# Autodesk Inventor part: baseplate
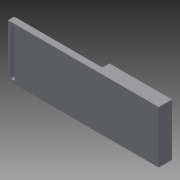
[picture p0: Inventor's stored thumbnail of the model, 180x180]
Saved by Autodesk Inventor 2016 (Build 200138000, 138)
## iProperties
Created: 2014-07
Part Number: baseplate
Material: Generic
Document SubType Name: Modeling
Designer: James
Density: 1 g/cm^3
Appearance: Default
Author: James
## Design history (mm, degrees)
sketch "Sketch1"
  geometry: L1 (-103.334, 41.944)-(116.666, 41.944); L2 (116.666, 41.944)-(116.666, -34.256); L3 (116.666, -34.256)-(-103.334, -34.256); L4 (-103.334, -34.256)-(-103.334, 41.944); 1 further point
  constraints: 8 end point, 2 parallel, 1 horizontal, 1 perpendicular
  dimensions: "d0" = 76.2 distance between parallel lines of L3 L1; "d1" = 220 distance between parallel lines of L2 L4
extrude "Extrusion1" new body sketch "Sketch1" distance "d2" = 10; taper "d3" = 0 deg
sketch "Sketch3"
  geometry: L1 (103.334, -41.944)-(103.334, 34.256) reference; L2 (103.334, 34.256)-(-116.666, 34.256) reference; L3 (103.334, 34.256)-(1.734, 34.256); L4 (1.734, 34.256)-(1.734, -41.944); L5 (1.734, -41.944)-(103.334, -41.944); L6 (103.334, -41.944)-(103.334, 34.256); 3 further points
  constraints: 8 end point, 2 parallel, 1 horizontal, 1 perpendicular
  dimensions: "d13" = 76.2 distance between parallel lines of L3 L5; "d14" = 101.6 distance between parallel lines of L1 L4; "d15" = 38.1 distance from line of L1 point (65.234, -3.844); "d16" = 38.1 distance from line of L2 point (65.234, -3.844); "d17" = 25.4 distance of point (65.234, -3.844) point (39.834, -3.844); "d18" = 38.1 distance from line of L2 point (39.834, -3.844)
extrude "Extrusion3" join sketch "Sketch3" distance "d26" = 11.5; taper "d27" = 0 deg
sketch "Sketch4"
  geometry: L1 (103.334, 34.256)-(1.734, 34.256) reference; L2 (103.334, -41.944)-(103.334, 34.256) reference; 3 further points
  dimensions: "d28" = 38.1 distance from line of L2 point (65.234, -3.844); "d29" = 38.1 distance from line of L1 point (65.234, -3.844); "d30" = 38.1 distance from line of L1 point (39.834, -3.844); "d31" = 25.4 distance of point (65.234, -3.844) point (39.834, -3.844)
hole "Hole2" sketch "Sketch4" at (65.234, -3.844), (39.834, -3.844) diameter "d32" = 4.917; stored, may be unused: countersink angle "d36" = 90 deg, drill point angle "d38" = 118 deg; dims "d33" = 6, "d34" = 4, "d35" = 2, "d37" = 15
sketch "Sketch7"
  geometry: L1 (1.734, -41.944)-(1.734, 34.256) reference; L2 (1.734, 34.256)-(-116.666, 34.256) reference; L3 (-116.666, -41.944)-(1.734, -41.944) reference; L4 (1.734, 6.111)-(-18.266, 6.111); L5 (-18.266, 6.111)-(-18.266, -10.434); L6 (-18.266, -10.434)-(1.734, -10.434); L7 (1.734, -10.434)-(1.734, 6.111); L8 (-18.266, -7.069)-(-64.266, -7.069); L9 (-64.266, -7.069)-(-64.266, -2.161); L10 (-64.266, -2.161)-(-18.266, -2.161); L11 (-18.266, -2.161)-(-18.266, -7.069); L12 (-64.266, 7.156)-(-64.266, -14.844); 3 further points
  constraints: 18 end point, 5 parallel, 2 coincident, 2 horizontal, 2 perpendicular, 2 point on line
  dimensions: "d46" = 20 distance between parallel lines of L7 L5; "d47" = 46 distance between parallel lines of L11 L9; "d48" = 27.1 distance from line of L3 L12.end; "d49" = 27.1 distance from line of L2 L12.start (= d48); "d57" = 0 distance between parallel lines of L12 L9
hole "Hole3" sketch "Sketch7" at (-64.266, 7.156), (-64.266, -14.844) diameter "d50" = 2.459; stored, may be unused: countersink angle "d54" = 90 deg, drill point angle "d56" = 118 deg; dims "d51" = 6, "d52" = 4, "d53" = 2, "d55" = 8
sketch "Sketch8"
  geometry: L1 (220, 0)-(0, 0) reference; L2 (220, 0)-(220, 10) reference; L3 (101.6, 10)-(220, 10) reference; L4 (101.6, 10)-(101.6, 21.5) reference; L5 (0, 21.5)-(101.6, 21.5) reference; L6 (0, 0)-(0, 21.5) reference; L7 (0, 21.5)-(0, 0); L8 (220, 0)-(220, 10); L9 (101.6, 10)-(220, 10); L10 (220, 0)-(0, 0); L11 (0, 21.5)-(101.6, 21.5); L12 (101.6, 10)-(101.6, 21.5); 1 further point
  constraints: 12 end point, 6 collinear
extrude "Extrusion5" join sketch "Sketch8" distance "d58" = 1; taper "d59" = 0 deg
sketch "Sketch9"
  geometry: L1 (220, 0)-(0, 0) reference; L2 (220, 0)-(220, 21.5) reference; L3 (118.4, 21.5)-(220, 21.5) reference; L4 (118.4, 10)-(118.4, 21.5) reference; L5 (0, 10)-(118.4, 10) reference; L6 (0, 10)-(0, 0); L7 (220, 0)-(220, 21.5); L8 (220, 21.5)-(118.4, 21.5); L9 (118.4, 21.5)-(118.4, 10); L10 (118.4, 10)-(0, 10); L11 (0, 0)-(220, 0); 1 further point
  constraints: 12 end point, 5 collinear, 1 perpendicular
extrude "Extrusion6" join sketch "Sketch9" distance "d60" = 1; taper "d61" = 0 deg
sketch "Sketch10"
  geometry: L1 (1.734, -42.944)-(1.734, 35.256) reference; L2 (1.734, -42.944)-(-116.666, -42.944) reference; L3 (-15.266, -30.944)-(-25.266, -30.944); L4 (-25.266, -30.944)-(-25.266, -42.944); L5 (-25.266, -42.944)-(-15.266, -42.944); L6 (-15.266, -42.944)-(-15.266, -30.944); L7 (-116.666, 35.256)-(1.734, 35.256) reference; 2 further points
  constraints: 8 end point, 2 parallel, 1 horizontal, 1 perpendicular, 1 point on line
  dimensions: "d62" = 17 distance between parallel lines of L1 L6; "d63" = 10 distance between parallel lines of L6 L4; "d65" = 12 distance between parallel lines of L2 L3; "d74" = 9 distance from line of L7 point (-22.266, 26.256); "d75" = 24 distance from line of L1 point (-22.266, 26.256)
hole "Hole4" sketch "Sketch10" at (-22.266, 26.256) diameter "d66" = 2.459; stored, may be unused: countersink angle "d70" = 90 deg, drill point angle "d72" = 118 deg; dims "d67" = 6, "d68" = 4, "d69" = 2, "d71" = 8
sketch "Sketch12"
  geometry: L1 (0, 0)-(220, 0) reference; L2 (220, 0)-(220, 21.5) reference; L3 (220, 21.5)-(118.4, 21.5) reference; L4 (118.4, 21.5)-(118.4, 10) reference; L5 (0, 0)-(118.4, 0); L6 (118.4, 0)-(118.4, 10); L7 (118.4, 10)-(0, 10); L8 (0, 10)-(0, 0); L9 (118.4, 0)-(220, 0); L10 (220, 0)-(220, 21.5); L11 (220, 21.5)-(118.4, 21.5); L12 (118.4, 21.5)-(118.4, 0); 1 further point
  constraints: 16 end point, 4 parallel, 2 horizontal, 2 perpendicular
extrude "Extrusion7" join sketch "Sketch12" distance "d86" = 15; taper "d87" = 0 deg
sketch "Sketch13"
  geometry: L1 (0, 10)-(93.2, 10); L2 (93.2, 10)-(93.2, 0); L3 (93.2, 0)-(0, 0); L4 (0, 0)-(0, 10); 1 further point
  constraints: 8 end point, 2 parallel, 1 horizontal, 1 perpendicular
extrude "Extrusion8" join sketch "Sketch13" distance "d88" = 23; taper "d89" = 0 deg
sketch "Sketch11"
  geometry: L1 (1.734, -42.944)-(-116.666, -42.944) reference; L2 (1.734, -57.944)-(1.734, 35.256) reference; 3 further points
  dimensions: "d76" = 7 distance from line of L1 point (-119.666, -35.944); "d78" = 96 distance of point (-119.666, -35.944) point (-23.666, -35.944); "d93" = 25.4 distance from line of point (-23.666, -35.944) L2; "d94" = 7 distance from line of L1 point (-23.666, -35.944)
hole "Hole5" sketch "Sketch11" at (-119.666, -35.944), (-23.666, -35.944) diameter "d79" = 2.459; stored, may be unused: countersink angle "d83" = 90 deg, drill point angle "d85" = 118 deg; dims "d80" = 6, "d81" = 4, "d82" = 2, "d84" = 8
sketch "Sketch6"
  geometry: L1 (1.734, -41.944)-(1.734, 34.256) reference; L2 (-134.266, 27.756)-(-134.266, -42.244); L3 (-137.666, 27.756)-(-137.666, -42.244); L4 (-130.866, -42.244)-(-130.866, 27.756); L5 (1.734, 35.256)-(-139.666, 35.256) reference; L6 (-139.666, -57.944)-(-139.666, 35.256) reference; A1 r 3.4 centre (-134.266, 27.756) between (-130.866, 27.756) and (-137.666, 27.756); A2 r 3.4 centre (-134.266, -42.244) between (-137.666, -42.244) and (-130.866, -42.244); 2 further points
  constraints: 8 end point, 4 point on circle, 4 tangent, 2 centre point, 2 parallel, 1 midpoint
  dimensions: "d40" = 3.4 distance between parallel lines of L3 L2; "d42" = 70 distance of L2.end L2.start (computed from d92); "d90" = 2 distance between parallel lines of L6 L3; "d91" = 42.5 distance from line of L5 point (-134.266, -7.244) (computed from d92); "d92" = 93.2 distance of L6.start L5.end (derived)
extrude "Extrusion4" cut sketch "Sketch6" distance "d44" = 11.5; taper "d45" = 0 deg
sketch "Sketch14"
  geometry: L1 (220, 0)-(-23, 0) reference; L2 (-23, 0)-(-23, 10) reference; 3 further points
  dimensions: "d95" = 5 distance from line of L1 point (119, 5); "d96" = 5 distance from line of L1 point (-1, 5); "d97" = 120 distance of point (-1, 5) point (119, 5); "d98" = 22 distance from line of point (-1, 5) L2
hole "Hole6" sketch "Sketch14" at (-1, 5), (119, 5) diameter "d99" = 2.459; stored, may be unused: countersink angle "d103" = 90 deg, drill point angle "d105" = 118 deg; dims "d100" = 6, "d101" = 4, "d102" = 2, "d104" = 8
workplane "Work Plane2"
mirror "Mirror2"
sketch "Sketch15"
  geometry: L1 (93.2, 0)-(93.2, 10) reference; L2 (93.2, 10)-(0, 10) reference; L3 (0, 10)-(93.2, 10); L4 (93.2, 10)-(93.2, 0); L5 (93.2, 0)-(0, 0); L6 (0, 0)-(0, 10); 1 further point
  constraints: 8 end point, 2 parallel, 1 horizontal, 1 perpendicular
extrude "Extrusion9" join sketch "Sketch15" distance "d106" = 2; taper "d107" = 0 deg
fillet "Fillet1" dims "d108" = 1.5
sketch "Sketch16"
  geometry: L1 (220, 0)-(-28.349, 0); L2 (-28.349, 0)-(-28.349, 21.618); L3 (-28.349, 21.618)-(220, 21.618); L4 (220, 21.618)-(220, 0); 1 further point
  constraints: 8 end point, 2 parallel, 1 horizontal, 1 perpendicular
extrude "Extrusion10" cut sketch "Sketch16" distance "d109" = 8.2; taper "d110" = 0 deg
sketch "Sketch17"
  geometry: L1 (0.234, 35.256)-(-140.166, 35.256) reference; L2 (-140.166, -49.744)-(0.234, -49.744) reference; L3 (-141.666, 35.256)-(-141.666, -49.744) reference; 5 further points
  dimensions: "d112" = 72 distance of point (-118.666, -41.744) point (-118.666, 30.256); "d113" = 75 distance of point (-118.666, 30.256) point (-43.666, 30.256); "d114" = 75 distance of point (-43.666, -41.744) point (-118.666, -41.744) (= d113); "d115" = 72 distance of point (-43.666, 30.256) point (-43.666, -41.744) (= d112); "d116" = 85 distance between parallel lines of L1 L2 (derived); "d117" = 8 distance from line of L2 point (-118.666, -41.744); "d118" = 8 distance from line of L2 point (-43.666, -41.744) (= d117); "d119" = 23 distance from line of L3 point (-118.666, -41.744); "d120" = 23 distance from line of L3 point (-118.666, 30.256) (= d119)
hole "Hole7" sketch "Sketch17" at (-43.666, -41.744), (-118.666, -41.744), (-118.666, 30.256), (-43.666, 30.256) diameter "d121" = 2.459; stored, may be unused: countersink angle "d125" = 90 deg, drill point angle "d127" = 118 deg; dims "d122" = 6, "d123" = 4, "d124" = 2, "d126" = 8
body "Solid1"
